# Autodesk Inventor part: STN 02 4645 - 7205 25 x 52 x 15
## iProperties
IsCustomPart: 0
Created: 2007-11
Part Number: STN 02 4645 - 7205 25 x 52 x 15
Material: Steel, Mild
Description: Angular Contact Ball Bearing
Document SubType Name: Modeling
Standard: STN 02 4645
Designer: CM
Standards Organization: STN
Language: en-US
Size Designation: 7205 25 x 52 x 15
Categories: <MemberInstance><Categories><Category DisplayName="Shaft Parts" InternalName="7f7aeb1f-a693-4053-b835-cee3144e0d98" Mnemonic="SHFT"><Category DisplayName="Beari
Density: 7.86 g/cm^3
Mass: 116.125 g
Surface Area: 104.153 cm^2
Volume: 14.7742 cm^3
Author: CM
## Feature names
1. Body [Revolution]
2. Fillet1
3. Ball [Revolution]
4. Balls [Circular Pattern]
